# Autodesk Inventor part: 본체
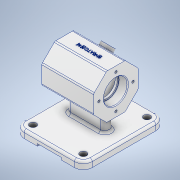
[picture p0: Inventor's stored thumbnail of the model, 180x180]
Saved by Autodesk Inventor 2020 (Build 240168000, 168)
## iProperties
Created: 2022-10
Part Number: 본체
Material: 알루미늄 6061
Document SubType Name: Modeling
Designer: 101-13
Mass: 558.501 g
Surface Area: 569.155 cm^2
Volume: 206.852 cm^3
Density: 2.7 g/cm^3
Appearance: 알루미늄 - 평지
Author: 101-13
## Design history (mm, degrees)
sketch "스케치1"
  geometry: L1 (46, -55)-(-46, -55); L2 (-46, -55)-(-46, 55); L3 (-46, 55)-(46, 55); L4 (46, 55)-(46, -55); L5 (46, -55)-(-46, 55); L6 (-46, -55)-(46, 55); 1 further point
  constraints: 12 end point, 2 midpoint, 2 parallel, 1 horizontal, 1 perpendicular
  dimensions: "d0" = 92 distance of L2.end L3.end; "d1" = 110 distance of L1.end L2.end
extrude "돌출1" new body sketch "스케치1" distance "d2" = 10; taper "d3" = 0 deg
fillet "모깎기1" dims "d4" = 12
node "작업 평면2"
sketch "스케치2"
  geometry: L1 (0, 0)-(86, 0) reference; L2 (-12, 10)-(-12, 0) reference; L3 (43, 62)-(43, 32); L4 (30.574, 92)-(55.426, 92); L5 (73, 74.426)-(73, 49.574); L6 (55.426, 32)-(30.574, 32); L7 (13, 49.574)-(13, 74.426); L8 (13, 92)-(73, 32); L9 (73, 92)-(13, 32); L10 (55.426, 32)-(73, 49.574); L11 (73, 74.426)-(55.426, 92); L12 (30.574, 92)-(13, 74.426); L13 (13, 49.574)-(30.574, 32); L14 (43, 19.574)-(43, 104.426); L15 (0, 62)-(0.574, 62); L16 (0, 0)-(-12, 0) reference; L17 (-12, 0)-(100.253, 0); L18 (-12, 62)-(100.253, 62); C1 r 30 at (43, 62)
  constraints: 30 end point, 7 parallel, 4 midpoint, 2 horizontal, 2 perpendicular, 1 centre point, 1 coincident
  dimensions: "d10" = 55 distance between parallel lines of L2 L3; "d12" = 60 distance of L8.end L9.end; "d82" = 62 distance between parallel lines of L17 L18
extrude "돌출2" join sketch "스케치2" stored distance "d14" = 70; taper "d15" = 0 deg
sketch "스케치9"
  geometry: L1 (20, 0)-(-20, 0); L2 (20, -6)-(-20, -6); L3 (-20, 6)-(20, 6); A1 r 6 centre (20, 0) between (20, -6) and (20, 6); A2 r 6 centre (-20, 0) between (-20, 6) and (-20, -6); 1 further point
  constraints: 8 end point, 4 point on circle, 4 tangent, 2 centre point, 1 midpoint, 1 parallel
extrude "돌출8" join sketch "스케치9" stored distance "d39" = 12; taper "d40" = 0 deg
sketch "스케치10"
  geometry: L1 (55.426, 92)-(30.574, 92) reference; L2 (43, 92)-(43, 32); L3 (55.426, 32)-(30.574, 32) reference; L4 (13, 74.426)-(13, 49.574) reference; L5 (73, 74.426)-(73, 49.574) reference; L6 (13, 62)-(73, 62); 6 further points
  constraints: 4 end point, 4 midpoint, 4 point on line
hole "구멍1" sketch "스케치10" at (43, 84.818), (20.001, 62), (43, 38.818), (65.999, 62) diameter "d42" = 3.242; stored, may be unused: countersink angle "d46" = 90 deg, drill point angle "d48" = 118 deg; dims "d43" = 8, "d44" = 4, "d45" = 2, "d47" = 10
sketch "스케치11"
  geometry: L1 (70, 0)-(70, -24.853) reference; L2 (35, 0)-(35, -24.853); L3 (0, -24.853)-(0, 0) reference; L4 (0, -12.426)-(70, -12.426); C1 r 8 at (35, -12.426); 1 further point
  constraints: 4 end point, 3 midpoint, 1 centre point, 1 parallel
  dimensions: "d49" = 35 distance between parallel lines of L1 L2; "d50" = 16 diameter of C1
extrude "돌출9" join sketch "스케치11" distance "d51" = 5; taper "d52" = 0 deg
sketch "스케치12"
  geometry: C1 r 4 at (0, 0); 1 further point
  constraints: 1 centre point
  dimensions: "d53" = 8 diameter of C1
extrude "돌출10" cut sketch "스케치12" distance "d54" = 30; taper "d55" = 0 deg
fillet "모깎기2" dims "d56" = 1
fillet "모깎기3" dims "d57" = 3
fillet "모깎기4" dims "d58" = 3
sketch "스케치13"
  geometry: L1 (18, 3)-(50, 3); L2 (50, 3)-(50, -3); L3 (50, -3)-(18, -3); L4 (18, -3)-(18, 3); L5 (18, 3)-(50, -3); L6 (50, 3)-(18, -3); 1 further point
  constraints: 12 end point, 2 midpoint, 2 parallel, 1 horizontal, 1 perpendicular
  dimensions: "d67" = 32 distance of L2.end L3.end; "d68" = 6 distance of L1.end L2.end
extrude "돌출11" cut sketch "스케치13" extent not by distance; stored distance "d69" = 0; taper "d70" = 0 deg
sketch "스케치14"
  geometry: C1 r 4.5 at (-34, -43); C2 r 4.5 at (34, -43); C3 r 4.5 at (34, 43); C4 r 4.5 at (-34, 43); A1 r 12 centre (-34, -43) between (-46, -43) and (-34, -55) reference; A2 r 12 centre (34, -43) between (34, -55) and (46, -43) reference; A3 r 12 centre (34, 43) between (46, 43) and (34, 55) reference; A4 r 12 centre (-34, 43) between (-34, 55) and (-46, 43) reference; 1 further point
  constraints: 4 centre point, 4 coincident
  dimensions: "d71" = 9 diameter of C1; "d72" = 9 diameter of C2; "d73" = 9 diameter of C3; "d74" = 9 diameter of C4
extrude "돌출12" cut sketch "스케치14" extent not by distance; stored distance "d75" = 0; taper "d76" = 0 deg
sketch "스케치15"
  geometry: L1 (51.159, 8.127)-(17.976, 8.127); L2 (17.976, 8.127)-(17.976, 12.93); L3 (17.976, 12.93)-(51.159, 12.93); L4 (51.159, 12.93)-(51.159, 8.127); 3 further points
  constraints: 1 coincident, 2 other
feature "엠보싱1" sketch "스케치15" dims "d0" = 92, "d1" = 110, "d10" = 55, "d12" = 60, "d77" = 0.5, "d78" = 0
fillet "모깎기7" dims "d79" = 3
sketch "스케치16"
  geometry: 1 further point
sketch "스케치17"
  geometry: L1 (-13.53, 0)-(106.864, 0); L2 (-13.53, 62)-(106.864, 62); L3 (43, 91.79)-(43, 0); C1 r 16 at (43, 62)
  constraints: 6 end point, 2 point on line, 1 centre point, 1 horizontal, 1 parallel, 1 vertical
  dimensions: "d80" = 62 distance between parallel lines of L1 L2; "d84" = 32 diameter of C1
extrude "돌출13" cut sketch "스케치17" distance "d85" = 12; taper "d86" = 0 deg
sketch "스케치18"
  geometry: C1 r 14 at (0, 0); 1 further point
  constraints: 1 centre point
  dimensions: "d87" = 28 diameter of C1
extrude "돌출14" cut sketch "스케치18" distance "d88" = 3; taper "d89" = 0 deg
sketch "스케치19"
  geometry: C1 r 25 at (0, 0); 1 further point
  constraints: 1 centre point
  dimensions: "d90" = 50 diameter of C1
extrude "돌출15" cut sketch "스케치19" distance "d91" = 40; taper "d92" = 0 deg
sketch "스케치20"
  geometry: C1 r 14 at (0, 0); 1 further point
  constraints: 1 centre point
  dimensions: "d93" = 28 diameter of C1
extrude "돌출16" cut sketch "스케치20" distance "d94" = 3; taper "d95" = 0 deg
sketch "스케치21"
  geometry: C1 r 16 at (0, 0); 1 further point
  constraints: 1 centre point
  dimensions: "d96" = 32 diameter of C1
extrude "돌출17" cut sketch "스케치21" distance "d97" = 12; taper "d98" = 0 deg
chamfer "모따기3" distance "d99" = 1; stored, may be unused: second distance "d100" = 2, angle "d101" = 45 deg
chamfer "모따기4" distance "d102" = 1; stored, may be unused: second distance "d103" = 2, angle "d104" = 45 deg
fillet "모깎기8" dims "d105" = 0.3
fillet "모깎기9" dims "d106" = 3
node "솔리드1"
mirror "미러1"
feature "A9D066F2-1C7D-4E18-AEED-F7BC21143FA4" dims "d42" = 3.242, "d43" = 8, "d44" = 4, "d45" = 2, "d46" = 90 deg, "d47" = 10, "d48" = 118 deg
other parameters: "d9" = 62
